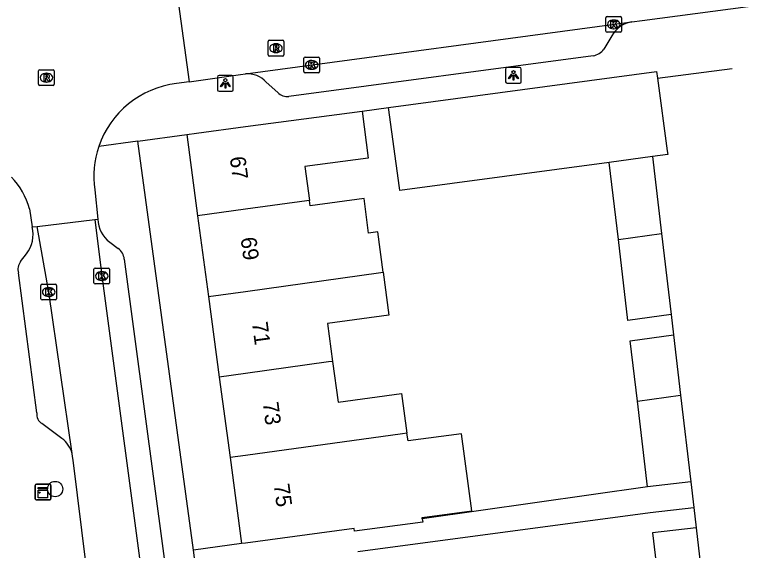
# Model space of a CAD drawing. Extents: x 163150 to 163546, y 380933 to 381635.
# Drawn here: x 163485.3 to 163532.22, y 381288.37 to 381322.5 of the extents above; entities that cross this region are included whole.
import ezdxf

# ---------------------------------------------------------------- set-up
doc = ezdxf.new("R2010")
doc.units = 0
for name, color, linetype in [('IMGEO_Boom', 7, 'Continuous'), ('IMGEO_Kast', 7, 'Continuous'), ('IMGEO_Kolk', 7, 'Continuous'), ('IMGEO_Lichtpunt', 7, 'Continuous'), ('IMGEO_Pand', 7, 'Continuous'), ('IMGEO_Pand_nummerreeks', 7, 'Continuous'), ('IMGEO_Rijbaan_lokaal_open', 7, 'Continuous'), ('IMGEO_Rioolput', 7, 'Continuous'), ('IMGEO_Voetpad_open', 7, 'Continuous')]:
    doc.layers.add(name, color=color, linetype=linetype)

msp = doc.modelspace()

# ---------------------------------------------------------------- linework, layer by layer
at = {"layer": 'IMGEO_Boom'}
msp.add_circle((163487.874, 381292.271), 0.489, dxfattribs=at)
at = {"layer": 'IMGEO_Kast'}
for p, q in [((163486.602, 381291.651), (163486.602, 381292.492)), ((163486.602, 381292.492), (163486.602, 381291.651)), ((163486.677, 381292.576), (163487.518, 381292.576)), ((163487.518, 381292.576), (163486.677, 381292.576)), ((163487.602, 381292.501), (163487.602, 381291.66)), ((163487.602, 381291.66), (163487.602, 381292.501)), ((163487.527, 381291.576), (163486.686, 381291.576)), ((163486.686, 381291.576), (163487.527, 381291.576))]:
    msp.add_line(p, q, dxfattribs=at)
for points in [[(163486.797, 381292.366), (163487.397, 381292.366), (163487.397, 381292.281), (163486.797, 381292.281), (163486.797, 381292.366)], [(163486.797, 381292.191), (163487.397, 381292.191), (163487.397, 381291.702), (163486.797, 381291.702), (163486.797, 381292.191)]]:
    msp.add_lwpolyline(points, dxfattribs=at)
msp.add_circle((163486.881, 381292.04), 0.0377, dxfattribs=at)
for centre, start, end in [((163486.68, 381292.498), 92.4484, 184.2845), ((163486.68, 381292.498), 92.4484, 184.2845), ((163487.524, 381292.498), 2.4484, 94.2845), ((163487.524, 381292.498), 2.4484, 94.2845), ((163486.68, 381291.654), 182.4484, 274.2845), ((163486.68, 381291.654), 182.4484, 274.2845), ((163487.524, 381291.654), 272.4484, 4.2845), ((163487.524, 381291.654), 272.4484, 4.2845)]:
    msp.add_arc(centre, 0.0779, start, end, dxfattribs=at)
at = {"layer": 'IMGEO_Kolk'}
for p, q in [((163522.964, 381321.459), (163522.964, 381322.311)), ((163523.039, 381322.385), (163523.891, 381322.385)), ((163523.452, 381322.165), (163523.477, 381322.165)), ((163523.965, 381322.311), (163523.965, 381321.459)), ((163523.475, 381321.605), (163523.45, 381321.605)), ((163523.891, 381321.385), (163523.039, 381321.385)), ((163503.72, 381318.877), (163503.72, 381319.729)), ((163503.795, 381319.803), (163504.647, 381319.803)), ((163504.721, 381319.729), (163504.721, 381318.877)), ((163504.208, 381319.583), (163504.233, 381319.583)), ((163504.647, 381318.803), (163503.795, 381318.803)), ((163504.231, 381319.023), (163504.206, 381319.023)), ((163490.346, 381305.423), (163490.346, 381306.275)), ((163490.421, 381306.349), (163491.273, 381306.349)), ((163490.834, 381306.129), (163490.859, 381306.129)), ((163491.347, 381306.275), (163491.347, 381305.423)), ((163486.966, 381304.396), (163486.966, 381305.248)), ((163487.041, 381305.322), (163487.893, 381305.322)), ((163487.967, 381305.248), (163487.967, 381304.396)), ((163491.273, 381305.349), (163490.421, 381305.349)), ((163490.857, 381305.569), (163490.832, 381305.569)), ((163487.454, 381305.102), (163487.479, 381305.102)), ((163487.893, 381304.322), (163487.041, 381304.322)), ((163487.477, 381304.542), (163487.452, 381304.542))]:
    msp.add_line(p, q, dxfattribs=at)
for points in [[(163522.964, 381321.459), (163522.964, 381322.311)], [(163523.039, 381322.385), (163523.891, 381322.385)], [(163523.285, 381322.085), (163523.408, 381322.085), (163523.408, 381321.934), (163523.538, 381322.085), (163523.702, 381322.085), (163523.556, 381321.934), (163523.709, 381321.685), (163523.557, 381321.685), (163523.472, 381321.849), (163523.408, 381321.782), (163523.408, 381321.685), (163523.285, 381321.685), (163523.285, 381322.085)], [(163523.965, 381322.311), (163523.965, 381321.459)], [(163523.891, 381321.385), (163523.039, 381321.385)], [(163503.72, 381318.877), (163503.72, 381319.729)], [(163503.795, 381319.803), (163504.647, 381319.803)], [(163504.721, 381319.729), (163504.721, 381318.877)], [(163504.041, 381319.503), (163504.164, 381319.503), (163504.164, 381319.352), (163504.294, 381319.503), (163504.458, 381319.503), (163504.312, 381319.352), (163504.465, 381319.103), (163504.313, 381319.103), (163504.228, 381319.267), (163504.164, 381319.2), (163504.164, 381319.103), (163504.041, 381319.103), (163504.041, 381319.503)], [(163504.647, 381318.803), (163503.795, 381318.803)], [(163490.346, 381305.423), (163490.346, 381306.275)], [(163490.421, 381306.349), (163491.273, 381306.349)], [(163491.347, 381306.275), (163491.347, 381305.423)], [(163490.667, 381306.049), (163490.79, 381306.049), (163490.79, 381305.898), (163490.92, 381306.049), (163491.084, 381306.049), (163490.938, 381305.898), (163491.091, 381305.649), (163490.939, 381305.649), (163490.854, 381305.813), (163490.79, 381305.746), (163490.79, 381305.649), (163490.667, 381305.649), (163490.667, 381306.049)], [(163486.966, 381304.396), (163486.966, 381305.248)], [(163487.041, 381305.322), (163487.893, 381305.322)], [(163487.967, 381305.248), (163487.967, 381304.396)], [(163491.273, 381305.349), (163490.421, 381305.349)], [(163487.287, 381305.022), (163487.41, 381305.022), (163487.41, 381304.871), (163487.54, 381305.022), (163487.704, 381305.022), (163487.558, 381304.871), (163487.711, 381304.622), (163487.559, 381304.622), (163487.474, 381304.786), (163487.41, 381304.719), (163487.41, 381304.622), (163487.287, 381304.622), (163487.287, 381305.022)], [(163487.893, 381304.322), (163487.041, 381304.322)]]:
    msp.add_lwpolyline(points, dxfattribs=at)
for centre, start, end in [((163523.041, 381322.309), 91.552, 178.448), ((163523.041, 381322.309), 91.552, 178.448), ((163523.889, 381322.309), 1.552, 88.448), ((163523.889, 381322.309), 1.552, 88.448), ((163523.041, 381321.461), 181.552, 268.448), ((163523.041, 381321.461), 181.552, 268.448), ((163523.889, 381321.461), 271.552, 358.448), ((163523.889, 381321.461), 271.552, 358.448), ((163503.797, 381319.727), 91.552, 178.448), ((163503.797, 381319.727), 91.552, 178.448), ((163504.645, 381319.727), 1.552, 88.448), ((163504.645, 381319.727), 1.552, 88.448), ((163503.797, 381318.879), 181.552, 268.448), ((163503.797, 381318.879), 181.552, 268.448), ((163504.645, 381318.879), 271.552, 358.448), ((163504.645, 381318.879), 271.552, 358.448), ((163490.423, 381306.273), 91.552, 178.448), ((163490.423, 381306.273), 91.552, 178.448), ((163491.271, 381306.273), 1.552, 88.448), ((163491.271, 381306.273), 1.552, 88.448), ((163487.043, 381305.246), 91.552, 178.448), ((163487.043, 381305.246), 91.552, 178.448), ((163487.891, 381305.246), 1.552, 88.448), ((163487.891, 381305.246), 1.552, 88.448), ((163490.423, 381305.425), 181.552, 268.448), ((163490.423, 381305.425), 181.552, 268.448), ((163491.271, 381305.425), 271.552, 358.448), ((163491.271, 381305.425), 271.552, 358.448), ((163487.043, 381304.398), 181.552, 268.448), ((163487.043, 381304.398), 181.552, 268.448), ((163487.891, 381304.398), 271.552, 358.448), ((163487.891, 381304.398), 271.552, 358.448)]:
    msp.add_arc(centre, 0.0765, start, end, dxfattribs=at)
for centre, major_axis, ratio, start_param, end_param in [((163523.451, 381321.885), (-0.387, 0.002), 0.722429, 4.712389, 7.853982), ((163523.476, 381321.885), (-0.39, 0.002), 0.717154, 1.570796, 4.712389), ((163504.207, 381319.303), (-0.387, 0.002), 0.722429, 4.712389, 7.853982), ((163504.232, 381319.303), (-0.39, 0.002), 0.717154, 1.570796, 4.712389), ((163490.833, 381305.849), (-0.387, 0.002), 0.722429, 4.712389, 7.853982), ((163490.858, 381305.849), (-0.39, 0.002), 0.717154, 1.570796, 4.712389), ((163487.453, 381304.822), (-0.387, 0.002), 0.722429, 4.712389, 7.853982), ((163487.478, 381304.822), (-0.39, 0.002), 0.717154, 1.570796, 4.712389)]:
    msp.add_ellipse(centre, major_axis=major_axis, ratio=ratio, start_param=start_param, end_param=end_param, dxfattribs=at)
at = {"layer": 'IMGEO_Lichtpunt'}
for p, q in [((163516.573, 381319.041), (163516.573, 381318.234)), ((163516.573, 381319.041), (163516.573, 381318.234)), ((163517.475, 381319.136), (163516.667, 381319.136)), ((163517.475, 381319.136), (163516.667, 381319.136)), ((163517.569, 381318.234), (163517.569, 381319.041)), ((163517.569, 381318.234), (163517.569, 381319.041)), ((163498.221, 381318.531), (163498.221, 381317.724)), ((163498.221, 381318.531), (163498.221, 381317.724)), ((163499.123, 381318.626), (163498.315, 381318.626)), ((163499.123, 381318.626), (163498.315, 381318.626)), ((163499.217, 381317.724), (163499.217, 381318.531)), ((163499.217, 381317.724), (163499.217, 381318.531)), ((163516.667, 381318.14), (163517.475, 381318.14)), ((163516.667, 381318.14), (163517.475, 381318.14)), ((163498.315, 381317.63), (163499.123, 381317.63)), ((163498.315, 381317.63), (163499.123, 381317.63))]:
    msp.add_line(p, q, dxfattribs=at)
for points in [[(163516.947, 381318.705), (163516.986, 381318.677), (163516.798, 381318.415), (163516.76, 381318.442), (163516.947, 381318.705)], [(163517.049, 381318.657), (163517.096, 381318.657), (163517.096, 381318.335), (163517.049, 381318.335), (163517.049, 381318.657)], [(163517.159, 381318.677), (163517.197, 381318.704), (163517.384, 381318.442), (163517.345, 381318.414), (163517.159, 381318.677)], [(163498.595, 381318.195), (163498.634, 381318.167), (163498.446, 381317.905), (163498.408, 381317.932), (163498.595, 381318.195)], [(163498.697, 381318.147), (163498.744, 381318.147), (163498.744, 381317.825), (163498.697, 381317.825), (163498.697, 381318.147)], [(163498.807, 381318.167), (163498.845, 381318.194), (163499.032, 381317.932), (163498.993, 381317.904), (163498.807, 381318.167)]]:
    msp.add_lwpolyline(points, dxfattribs=at)
for centre in [(163517.072, 381318.839), (163498.72, 381318.329)]:
    msp.add_circle(centre, 0.0994, dxfattribs=at)
for centre, start, end in [((163516.667, 381319.041), 90, 180), ((163516.667, 381319.041), 90, 180), ((163517.475, 381319.041), 0, 90), ((163517.475, 381319.041), 0, 90), ((163498.315, 381318.531), 90, 180), ((163498.315, 381318.531), 90, 180), ((163499.123, 381318.531), 0, 90), ((163499.123, 381318.531), 0, 90), ((163516.667, 381318.234), 180, 270), ((163516.667, 381318.234), 180, 270), ((163517.475, 381318.234), 270, 0), ((163517.475, 381318.234), 270, 360), ((163498.315, 381317.724), 180, 270), ((163498.315, 381317.724), 180, 270), ((163499.123, 381317.724), 270, 0), ((163499.123, 381317.724), 270, 360)]:
    msp.add_arc(centre, 0.0946, start, end, dxfattribs=at)
at = {"layer": 'IMGEO_Pand'}
for points in [[(163509.122, 381316.592), (163526.192, 381318.885), (163526.248, 381318.462)], [(163526.248, 381318.462), (163526.867, 381313.827), (163526.899, 381313.591), (163525.933, 381313.462)], [(163523.178, 381313.092), (163509.829, 381311.3), (163509.807, 381311.462), (163509.122, 381316.592)], [(163496.257, 381314.866), (163496.878, 381314.949), (163500, 381315.368), (163507.426, 381316.365)], [(163507.426, 381316.365), (163507.826, 381313.367), (163503.792, 381312.828), (163504.081, 381310.668)], [(163496.257, 381314.866), (163496.953, 381309.68)], [(163525.933, 381313.462), (163523.178, 381313.092)], [(163525.933, 381313.462), (163526.511, 381308.547)], [(163523.757, 381308.165), (163523.178, 381313.092)], [(163508.778, 381306.087), (163508.435, 381308.656), (163507.848, 381308.578), (163507.551, 381310.789), (163504.126, 381310.33), (163504.081, 381310.668)], [(163504.081, 381310.668), (163503.902, 381310.643), (163500, 381310.102), (163496.953, 381309.68)], [(163496.953, 381309.68), (163497.642, 381304.544)], [(163523.757, 381308.165), (163526.511, 381308.547)], [(163526.511, 381308.547), (163527.116, 381303.397)], [(163527.116, 381303.397), (163524.363, 381303.016), (163523.757, 381308.165)], [(163497.642, 381304.544), (163500, 381304.87), (163508.624, 381306.066), (163508.778, 381306.087)], [(163508.778, 381306.087), (163509.142, 381303.362), (163505.221, 381302.826), (163505.549, 381300.408)], [(163497.642, 381304.544), (163498.332, 381299.408)], [(163524.968, 381297.87), (163524.517, 381301.709), (163527.27, 381302.09)], [(163527.27, 381302.09), (163527.721, 381298.252)], [(163505.549, 381300.408), (163505.296, 381300.373), (163500, 381299.639), (163498.332, 381299.408)], [(163505.549, 381300.408), (163505.901, 381297.81), (163509.948, 381298.359), (163510.29, 381295.834)], [(163498.332, 381299.408), (163499.021, 381294.272)], [(163524.968, 381297.87), (163527.721, 381298.252)], [(163527.721, 381298.252), (163528.371, 381292.726)], [(163525.611, 381292.402), (163524.968, 381297.87)], [(163510.29, 381295.834), (163510.008, 381295.795), (163500, 381294.407), (163499.021, 381294.272)], [(163511.262, 381290.373), (163511.251, 381290.454), (163514.431, 381290.881), (163513.772, 381295.791), (163510.358, 381295.333), (163510.29, 381295.834)], [(163499.021, 381294.272), (163499.757, 381288.789)], [(163528.371, 381292.726), (163525.611, 381292.402)], [(163511.262, 381290.373), (163511.289, 381290.168), (163506.951, 381289.586), (163506.927, 381289.76), (163504.721, 381289.462), (163500, 381288.822), (163499.757, 381288.789)], [(163528.71, 381289.796), (163525.939, 381289.473), (163526.375, 381285.729)], [(163528.71, 381289.796), (163529.141, 381286.094)]]:
    msp.add_lwpolyline(points, dxfattribs=at)
at = {"layer": 'IMGEO_Rijbaan_lokaal_open'}
for points in [[(163495.731, 381323.177), (163496.421, 381318.221)], [(163524.612, 381322.04), (163525.264, 381322.126), (163532.015, 381323.02), (163532.223, 381323.048)], [(163500, 381318.735), (163524.612, 381322.04)], [(163526.248, 381318.462), (163531.005, 381319.076)], [(163496.421, 381318.221), (163499.683, 381318.682), (163500, 381318.735)], [(163496.421, 381318.221), (163495.598, 381318.116)], [(163490.394, 381311.344), (163490.584, 381309.465)], [(163486.239, 381310.132), (163486.415, 381308.977)], [(163486.73, 381309.012), (163490.402, 381309.443)], [(163490.402, 381309.443), (163490.584, 381309.465)], [(163490.402, 381309.443), (163490.846, 381305.849), (163493.759, 381284.035), (163496.541, 381263.222), (163497.43, 381256.373)], [(163486.415, 381308.977), (163486.73, 381309.012)], [(163488.958, 381294.533), (163487.468, 381304.821), (163486.73, 381309.012)], [(163527.116, 381303.397), (163527.27, 381302.09)], [(163490.149, 381285.047), (163490.135, 381285.185), (163489.02, 381294.106), (163488.987, 381294.337), (163488.958, 381294.533)], [(163528.371, 381292.726), (163528.559, 381291.089)], [(163528.559, 381291.089), (163528.71, 381289.796)]]:
    msp.add_lwpolyline(points, dxfattribs=at)
for centre, radius, start, end in [((163496.315, 381312.18), 5.979, 96.8899, 161.2586), ((163496.325, 381312.178), 5.989, 161.2665, 187.9999), ((163481.488, 381308.784), 4.939, 15.8417, 43.0298)]:
    msp.add_arc(centre, radius, start, end, dxfattribs=at)
at = {"layer": 'IMGEO_Rioolput'}
for p, q in [((163501.443, 381319.944), (163501.443, 381320.796)), ((163501.518, 381320.87), (163502.37, 381320.87)), ((163501.931, 381320.65), (163501.956, 381320.65)), ((163502.444, 381320.796), (163502.444, 381319.944)), ((163502.37, 381319.87), (163501.518, 381319.87)), ((163501.954, 381320.09), (163501.929, 381320.09)), ((163486.82, 381318.067), (163486.82, 381318.919)), ((163486.895, 381318.993), (163487.747, 381318.993)), ((163487.308, 381318.773), (163487.333, 381318.773)), ((163487.821, 381318.919), (163487.821, 381318.067)), ((163487.747, 381317.993), (163486.895, 381317.993)), ((163487.331, 381318.213), (163487.306, 381318.213))]:
    msp.add_line(p, q, dxfattribs=at)
for points in [[(163501.443, 381319.944), (163501.443, 381320.796)], [(163501.518, 381320.87), (163502.37, 381320.87)], [(163502.444, 381320.796), (163502.444, 381319.944)], [(163502.032, 381320.568), (163501.78, 381320.57), (163501.78, 381320.17)], [(163501.78, 381320.17), (163501.904, 381320.17), (163501.904, 381320.332), (163501.915, 381320.332)], [(163501.958, 381320.489), (163501.904, 381320.489), (163501.904, 381320.408)], [(163501.904, 381320.408), (163501.956, 381320.408)], [(163501.962, 381320.303), (163502.033, 381320.17), (163502.173, 381320.17), (163502.108, 381320.296)], [(163502.37, 381319.87), (163501.518, 381319.87)], [(163486.82, 381318.067), (163486.82, 381318.919)], [(163486.895, 381318.993), (163487.747, 381318.993)], [(163487.821, 381318.919), (163487.821, 381318.067)], [(163487.409, 381318.691), (163487.157, 381318.693), (163487.157, 381318.293)], [(163487.157, 381318.293), (163487.281, 381318.293), (163487.281, 381318.455), (163487.292, 381318.455)], [(163487.335, 381318.612), (163487.281, 381318.612), (163487.281, 381318.531)], [(163487.281, 381318.531), (163487.333, 381318.531)], [(163487.339, 381318.426), (163487.41, 381318.293), (163487.55, 381318.293), (163487.485, 381318.419)], [(163487.747, 381317.993), (163486.895, 381317.993)]]:
    msp.add_lwpolyline(points, dxfattribs=at)
for centre, radius, start, end in [((163501.52, 381320.794), 0.0765, 91.552, 178.448), ((163501.52, 381320.794), 0.0765, 91.552, 178.448), ((163502.368, 381320.794), 0.0765, 1.552, 88.448), ((163502.368, 381320.794), 0.0765, 1.552, 88.448), ((163501.914, 381320.279), 0.0533, 26.0293, 88.6989), ((163501.94, 381320.597), 0.19, 274.7715, 282.9687), ((163501.964, 381320.393), 0.0964, 77.0061, 93.1865), ((163501.978, 381320.45), 0.0378, 276.6634, 79.6772), ((163502.031, 381320.458), 0.109, 350.3612, 89.416), ((163502.029, 381320.458), 0.112, 277.5842, 350.9817), ((163502.013, 381320.243), 0.108, 29.5134, 73.7905), ((163501.52, 381319.946), 0.0765, 181.552, 268.448), ((163501.52, 381319.946), 0.0765, 181.552, 268.448), ((163502.368, 381319.946), 0.0765, 271.552, 358.448), ((163502.368, 381319.946), 0.0765, 271.552, 358.448), ((163486.897, 381318.917), 0.0765, 91.552, 178.448), ((163486.897, 381318.917), 0.0765, 91.552, 178.448), ((163487.745, 381318.917), 0.0765, 1.552, 88.448), ((163487.745, 381318.917), 0.0765, 1.552, 88.448), ((163487.291, 381318.402), 0.0533, 26.0293, 88.6989), ((163487.317, 381318.72), 0.19, 274.7715, 282.9687), ((163487.341, 381318.516), 0.0964, 77.0061, 93.1865), ((163487.355, 381318.573), 0.0378, 276.6634, 79.6772), ((163487.408, 381318.581), 0.109, 350.3612, 89.416), ((163487.406, 381318.581), 0.112, 277.5842, 350.9817), ((163487.39, 381318.366), 0.108, 29.5134, 73.7905), ((163486.897, 381318.069), 0.0765, 181.552, 268.448), ((163486.897, 381318.069), 0.0765, 181.552, 268.448), ((163487.745, 381318.069), 0.0765, 271.552, 358.448), ((163487.745, 381318.069), 0.0765, 271.552, 358.448)]:
    msp.add_arc(centre, radius, start, end, dxfattribs=at)
for centre, major_axis, ratio, start_param, end_param in [((163501.93, 381320.37), (-0.387, 0.002), 0.722429, 4.712389, 7.853982), ((163501.955, 381320.37), (-0.39, 0.002), 0.717154, 1.570796, 4.712389), ((163487.307, 381318.493), (-0.387, 0.002), 0.722429, 4.712389, 7.853982), ((163487.332, 381318.493), (-0.39, 0.002), 0.717154, 1.570796, 4.712389)]:
    msp.add_ellipse(centre, major_axis=major_axis, ratio=ratio, start_param=start_param, end_param=end_param, dxfattribs=at)
at = {"layer": 'IMGEO_Voetpad_open'}
for points in [[(163523.34, 381321.154), (163522.828, 381320.305)], [(163522.155, 381319.882), (163502.768, 381317.294)], [(163502.055, 381317.543), (163501.319, 381318.211)], [(163507.426, 381316.365), (163509.122, 381316.592)], [(163493.134, 381314.437), (163496.257, 381314.866)], [(163493.134, 381314.437), (163490.653, 381314.101)], [(163496.679, 381288.37), (163493.134, 381314.437)], [(163491.355, 381308.001), (163491.895, 381307.604)], [(163485.676, 381306.763), (163486.058, 381307.255)], [(163492.278, 381306.923), (163499.864, 381250), (163500, 381248.982), (163504.96, 381211.766)], [(163486.711, 381297.124), (163485.536, 381306.044)], [(163488.311, 381295.492), (163487.037, 381296.437)], [(163525.611, 381292.402), (163511.262, 381290.373)], [(163507.155, 381288.296), (163525.788, 381290.766), (163528.559, 381291.089)], [(163499.757, 381288.789), (163496.679, 381288.37)], [(163496.878, 381286.909), (163496.679, 381288.37)]]:
    msp.add_lwpolyline(points, dxfattribs=at)
for centre, radius, start, end in [((163524.884, 381320.293), 1.768, 98.8615, 150.8561), ((163521.96, 381320.939), 1.075, 280.4549, 323.8462), ((163500.105, 381317.077), 1.662, 43.0537, 93.6134), ((163502.673, 381318.166), 0.878, 225.2638, 276.2349), ((163492.583, 381309.583), 2.002, 183.3669, 232.1792), ((163484.387, 381308.499), 2.083, 323.3229, 13.2522), ((163491.313, 381306.828), 0.97, 5.5962, 53.1113), ((163486.279, 381306.272), 0.777, 140.8729, 197.0901), ((163487.414, 381297.037), 0.708, 172.9172, 237.854), ((163487.227, 381294.063), 1.794, 15.1929, 52.8191)]:
    msp.add_arc(centre, radius, start, end, dxfattribs=at)

# ---------------------------------------------------------------- texts
at = {"layer": 'IMGEO_Pand_nummerreeks'}
for s, rotation, p in [('67', 277.6444, (163498.994, 381313.412)), ('69', 277.643, (163499.687, 381308.267)), ('71', 277.6444, (163500.409, 381302.869)), ('73', 277.6444, (163501.094, 381297.766)), ('75', 277.643, (163501.795, 381292.55))]:
    msp.add_text(s, height=1, rotation=rotation, dxfattribs=at).set_placement(p)

doc.saveas('drawing.dxf')
